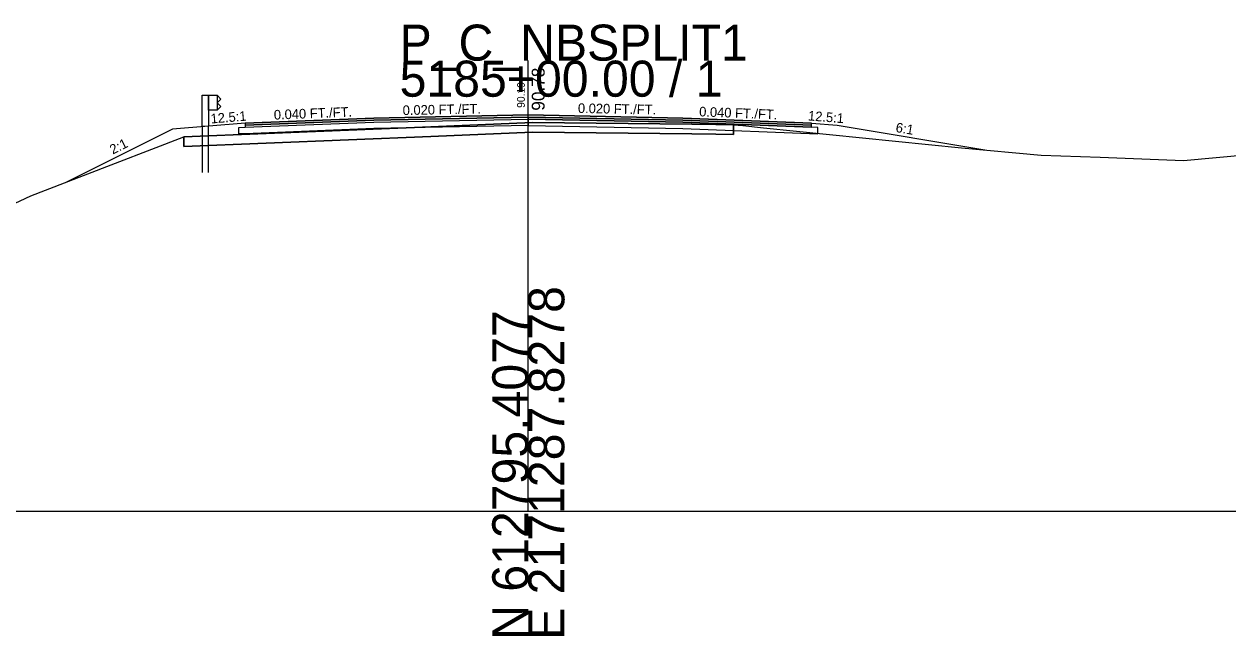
# Model space of a CAD drawing. Extents: x -26 to 1303, y -3010 to 12038.
# Drawn here: x 110.8 to 204.4, y 5990.3 to 6037.8 of the extents above; entities that cross this region are included whole.
import ezdxf

# ---------------------------------------------------------------- set-up
doc = ezdxf.new("R2010")
doc.units = 0
for name, color, linetype in [('RD_GPK_XS_Cell', 7, 'Continuous'), ('RD_PD_Final_TrvlWay', 7, 'Continuous'), ('RD_XS_Base', 7, 'Continuous'), ('RD_XS_ExGround', 7, 'Continuous'), ('RD_XS_ExPaveRet', 7, 'Continuous'), ('RD_XS_GR', 7, 'Continuous'), ('RD_XS_Greenside', 7, 'Continuous'), ('RD_XS_Pave', 7, 'Continuous'), ('RD_XS_PaveOvlay_CP', 7, 'Continuous'), ('RD_XS_TieSlope', 7, 'Continuous'), ('RD_XS_TX_Elev_EX', 7, 'Continuous'), ('RD_XS_TX_Elev_PR', 7, 'Continuous'), ('RD_XS_TX_ShdSlope', 7, 'Continuous'), ('RD_XS_TX_Slope', 7, 'Continuous')]:
    doc.layers.add(name, color=color, linetype=linetype)

msp = doc.modelspace()

# ---------------------------------------------------------------- linework, layer by layer
at = {"layer": 'RD_GPK_XS_Cell'}
for p, q in [((150, 6000), (150, 6035)), ((0, 6000), (150, 6000)), ((150, 6000), (300, 6000))]:
    msp.add_line(p, q, dxfattribs=at)
at = {"layer": 'RD_PD_Final_TrvlWay'}
for p, q in [((125.167, 6029.913), (124.667, 6029.873)), ((124.667, 6029.873), (124.667, 6026.308)), ((125.167, 6026.308), (125.167, 6029.913))]:
    msp.add_line(p, q, dxfattribs=at)
at = {"layer": 'RD_XS_Base'}
for p, q in [((150, 6030.462), (150, 6030.621)), ((150, 6030.621), (150, 6029.962)), ((127.5, 6029.802), (128, 6029.822)), ((127.5, 6029.302), (127.5, 6029.802)), ((127.5, 6029.802), (127.5, 6029.802)), ((128, 6029.822), (138, 6030.222)), ((128, 6029.822), (128, 6029.822)), ((138, 6029.722), (128, 6029.322)), ((138, 6030.222), (150, 6030.462)), ((138, 6030.222), (138, 6030.222)), ((150, 6029.962), (138, 6029.722)), ((138, 6029.722), (138, 6029.722)), ((150, 6030.462), (150, 6029.962)), ((162, 6030.222), (150, 6030.462)), ((150, 6030.462), (150, 6030.462)), ((150, 6029.962), (150, 6029.962)), ((150, 6029.962), (150, 6029.962)), ((150, 6029.962), (162, 6029.722)), ((172, 6029.822), (162, 6030.222)), ((162, 6029.722), (172.5, 6029.302)), ((164, 6030.142), (164, 6030.142)), ((164, 6029.642), (164, 6029.642)), ((172.5, 6029.802), (172, 6029.822)), ((172, 6029.822), (172, 6029.822)), ((172.5, 6029.302), (172.5, 6029.802)), ((172.5, 6029.802), (172.5, 6029.802)), ((128, 6029.322), (127.5, 6029.302)), ((127.5, 6029.302), (127.5, 6029.302)), ((127.5, 6029.302), (127.5, 6029.302)), ((128, 6029.322), (128, 6029.322)), ((172.5, 6029.302), (172.5, 6029.302)), ((172.5, 6029.302), (172.5, 6029.302))]:
    msp.add_line(p, q, dxfattribs=at)
at = {"layer": 'RD_XS_ExGround'}
msp.add_lwpolyline([(109.294, 6023.546), (111.364, 6024.488), (115.433, 6026.086), (123.249, 6029.084), (142.432, 6029.869), (150.315, 6030.207), (162.715, 6030.061), (164.58, 6030.039), (165.948, 6030.018), (166.673, 6029.972), (168.282, 6029.786), (181.079, 6028.495), (183.651, 6028.219), (189.849, 6027.663), (194.429, 6027.502), (200.9, 6027.237), (210.772, 6028.157)], dxfattribs=at)
at = {"layer": 'RD_XS_ExPaveRet'}
for p, q in [((142.432, 6029.869), (123.249, 6029.084)), ((150.315, 6030.207), (142.432, 6029.869)), ((162.715, 6030.061), (150.315, 6030.207)), ((164.58, 6030.039), (162.715, 6030.061))]:
    msp.add_line(p, q, dxfattribs=at)
for points in [[(164.58, 6030.039), (165.948, 6030.018), (165.948, 6029.268), (165.948, 6029.268), (164.58, 6029.289), (162.715, 6029.311), (162.715, 6029.311), (162.715, 6029.311), (150.315, 6029.457), (150.315, 6029.457), (150.315, 6029.457), (142.432, 6029.119), (142.432, 6029.119), (123.249, 6028.334), (123.249, 6029.084), (123.249, 6029.084), (142.432, 6029.869), (142.432, 6029.869), (150.315, 6030.207), (150.315, 6030.207), (150.315, 6030.207), (162.715, 6030.061), (162.715, 6030.061), (162.715, 6030.061), (164.58, 6030.039)], [(123.249, 6029.084), (123.249, 6028.334), (142.432, 6029.119), (150.315, 6029.457), (162.715, 6029.311), (164.58, 6029.289), (165.948, 6029.268), (165.948, 6030.018), (164.58, 6030.039)]]:
    msp.add_lwpolyline(points, dxfattribs=at)
at = {"layer": 'RD_XS_GR'}
for points in [[(125.167, 6032.308), (125.167, 6029.913), (124.667, 6029.873), (124.667, 6032.308), (124.917, 6032.308), (125.167, 6032.308)], [(125.834, 6032.308), (125.834, 6031.142), (125.167, 6031.142), (125.167, 6032.308), (125.834, 6032.308)], [(126.105, 6032.017), (125.834, 6032.308), (125.834, 6031.142), (125.834, 6031.142), (125.834, 6031.142), (126.105, 6031.433), (126.105, 6031.433), (125.834, 6031.725), (125.834, 6031.725), (126.105, 6032.017), (126.105, 6032.017)]]:
    msp.add_lwpolyline(points, dxfattribs=at)
at = {"layer": 'RD_XS_Greenside'}
for p, q in [((122.355, 6029.688), (114.112, 6025.567)), ((174, 6029.98), (185.631, 6028.042))]:
    msp.add_line(p, q, dxfattribs=at)
at = {"layer": 'RD_XS_Pave'}
for p, q in [((138, 6030.54), (128, 6030.14)), ((150, 6030.78), (138, 6030.54)), ((150, 6030.621), (138, 6030.381)), ((138, 6030.381), (150, 6030.621)), ((138, 6030.54), (138, 6030.54)), ((162, 6030.54), (150, 6030.78)), ((150, 6030.462), (150, 6030.621)), ((150, 6030.621), (162, 6030.381)), ((162, 6030.381), (150, 6030.621)), ((150, 6030.621), (150, 6030.462)), ((172, 6030.14), (162, 6030.54)), ((138, 6030.381), (128, 6029.981)), ((128, 6029.981), (138, 6030.381)), ((128, 6029.822), (138, 6030.222)), ((128, 6030.14), (128, 6030.14)), ((128, 6030.14), (128, 6029.981)), ((128, 6029.981), (128, 6029.981)), ((128, 6029.981), (128, 6029.822)), ((128, 6029.981), (128, 6029.981)), ((128, 6029.981), (128, 6029.981)), ((128, 6029.822), (128, 6029.822)), ((128, 6029.822), (128, 6029.822)), ((138, 6030.222), (150, 6030.462)), ((138, 6030.381), (138, 6030.381)), ((138, 6030.381), (138, 6030.381)), ((138, 6030.222), (138, 6030.222)), ((150, 6030.462), (150, 6030.462)), ((150, 6030.462), (150, 6030.462)), ((150, 6030.462), (162, 6030.222)), ((162, 6030.381), (172, 6029.981)), ((172, 6029.981), (162, 6030.381)), ((162, 6030.222), (172, 6029.822)), ((164, 6030.46), (164, 6030.46)), ((164, 6030.301), (164, 6030.301)), ((164, 6030.301), (164, 6030.301)), ((164, 6030.142), (164, 6030.142)), ((172, 6029.981), (172, 6030.14)), ((172, 6030.14), (172, 6030.14)), ((172, 6029.981), (172, 6029.981)), ((172, 6029.981), (172, 6029.981)), ((172, 6029.822), (172, 6029.981)), ((172, 6029.981), (172, 6029.981)), ((172, 6029.822), (172, 6029.822)), ((172, 6029.822), (172, 6029.822))]:
    msp.add_line(p, q, dxfattribs=at)
at = {"layer": 'RD_XS_PaveOvlay_CP'}
for p, q in [((128, 6030.14), (138, 6030.54)), ((138, 6030.54), (150, 6030.78)), ((150, 6030.78), (162, 6030.54)), ((162, 6030.54), (172, 6030.14))]:
    msp.add_line(p, q, dxfattribs=at)
at = {"layer": 'RD_XS_TieSlope'}
for p, q in [((128, 6030.14), (122.355, 6029.688)), ((172, 6030.14), (174, 6029.98))]:
    msp.add_line(p, q, dxfattribs=at)

# ---------------------------------------------------------------- texts
at = {"layer": 'RD_GPK_XS_Cell'}
for s, p in [('P_C_NBSPLIT1', (140, 6035)), ('5185+00.00 / 1', (140, 6032.2))]:
    msp.add_text(s, height=2.8, dxfattribs=at).set_placement(p)
for s, p in [('E 2171287.8278', (152.8, 5990)), ('N 612795.4077', (150, 5990))]:
    msp.add_text(s, height=2.8, rotation=90, dxfattribs=at).set_placement(p)
at = {"layer": 'RD_XS_TX_Elev_EX'}
msp.add_text('90.19', height=0.6, rotation=90, dxfattribs=at).set_placement((149.727, 6031.33))
at = {"layer": 'RD_XS_TX_Elev_PR'}
msp.add_text('90.78', height=1, rotation=90, dxfattribs=at).set_placement((151.267, 6031.113))
at = {"layer": 'RD_XS_TX_ShdSlope'}
for rotation, p in [(4.57392, (125.35, 6030.117)), (355.42608, (171.711, 6030.36))]:
    msp.add_text('12.5:1', height=0.75, rotation=rotation, dxfattribs=at).set_placement(p)
at = {"layer": 'RD_XS_TX_Slope'}
for s, rotation, p in [('0.020 FT./FT.', 1.14576, (140.248, 6030.77)), ('0.020 FT./FT.', 358.85424, (153.849, 6030.939)), ('0.040 FT./FT.', 357.70939, (163.262, 6030.675)), ('0.040 FT./FT.', 2.29061, (130.247, 6030.415)), ('6:1', 350.53768, (178.501, 6029.463)), ('2:1', 26.56505, (117.715, 6027.697))]:
    msp.add_text(s, height=0.75, rotation=rotation, dxfattribs=at).set_placement(p)

doc.saveas('drawing.dxf')
